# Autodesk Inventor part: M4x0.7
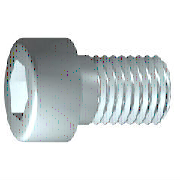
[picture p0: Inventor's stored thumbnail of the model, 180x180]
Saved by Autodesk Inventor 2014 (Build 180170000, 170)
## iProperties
Created: 2009-02
Part Number: M4x0.7
Material: Steel, Mild
Description: 6각머리 태핑 나사
Document SubType Name: Modeling
Standard: KS B 1003
Standards Organization: KS
Language: ko-KR
Size Designation: M 4 x 12
Categories: <MemberInstance><Categories><Category DisplayName="조임쇠" InternalName="e4da775c-781d-43d5-af7c-5136215cf5a6" Mnemonic="FSTN"><Category DisplayName="볼트" InternalN
Density: 1 g/cm^3
Checked By: KYOUNG IL JANG
Vendor: CBT Solutions
Designer: KYOUNG IL JANG
Appearance: _시험-금속-강(연마)
Manager: KYOUNG IL JANG
Company: 한국ATC센터
IsCustomPart: 0
Author: KYOUNG IL JANG
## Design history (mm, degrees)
revolve "본체" stored, may be unused: angle "d10" = 90 deg
sketch "스케치2"
  geometry: L1 (0, -4.9)-(0, 4.9) reference; L2 (-4.9, 0)-(4.9, 0) reference; L3 (1.732, 0)-(0.866, -1.5); L4 (0.866, -1.5)-(-0.866, -1.5); L5 (-0.866, -1.5)-(-1.732, 0); L6 (-1.732, 0)-(-0.866, 1.5); L7 (-0.866, 1.5)-(0.866, 1.5); L8 (0.866, 1.5)-(1.732, 0); 2 further points
  constraints: 12 end point, 1 coincident, 1 horizontal alignment, 1 point on line, 12 other
extrude "슬롯" join sketch "스케치2" stored distance "d11" = 10; taper "d12" = 0 deg
workplane "Work Plane1"
fillet "Fillet2" dims "d30" = 0.1 (= R)
body "Solid1"
fillet "모깎기1" dims "d17" = 0.4 (= RR)
feature "스레드" dims "d13" = 10.25 (= GEL), "d14" = 0
chamfer "모따기1" distance "d15" = 0.42941 (= -0.5 x SPD + 0.5 x GD); stored, may be unused: second distance "d16" = 0.42941 (= GUL), angle "d27" = 45 deg
sketch "스케치1"
  geometry: L1 (-1, 0)-(12, 0); L2 (12, 0)-(12, 2); L3 (12, 2)-(1.75, 2); L4 (1.75, 2)-(1.32, 2); L5 (1.32, 2)-(0, 2); L6 (0, 2)-(0, 3.5); L7 (0, 3.5)-(-4, 3.5); L8 (-4, 3.5)-(-4, 1.732); L9 (-4, 1.732)-(-2, 1.732); L10 (-2, 1.732)-(-1, 0); L11 (-7.2, 0)-(15.2, 0) reference; L12 (0, -0.7)-(0, 4.2) reference; L13 (1.75, 2)-(0, 2)
  constraints: 22 end point, 6 parallel, 2 collinear, 2 perpendicular, 1 horizontal, 1 point on line
  dimensions: "d1" = 10.25 distance from line of L3.end L2 (= GEL); "d2" = 0.42952 distance of L4.end L3.end (computed from GAL); "d3" = 4 distance between parallel lines of L8 L6 (= KOH); "d4" = 2 distance of L8.end L9.end (= INTI); "d5" = 60 deg angle of L10 L1; "d6" = 4 diameter of L3 L1 (= GD); "d7" = 4 diameter of L5 L1 (= BDM); "d8" = 3.4641 diameter of L9 L1 (= 1.1547 x SW); "d9" = 7 diameter of L7 L1 (= KOD); "d26" = 12 distance between parallel lines of L12 L2 (= NLG)
other parameters: "GD" = 4 (= NND) [user parameter; used in 2 equation terms], "NLG" = 12 [user parameter; used in 1 equation term], "GEL" = 10.25 [user parameter; used in 2 equation terms], "KOD" = 7 [user parameter; used in 1 equation term], "KOH" = 4 [user parameter; used in 1 equation term], "INTI" = 2 [user parameter; used in 1 equation term], "GAL" = 0.42941 (= 0.61345 x PTC) [user parameter; used in 1 equation term], "GUL" = 0.42941 (= 0.61345 x PTC) [user parameter; used in 1 equation term], "BDM" = 4 (= NND) [user parameter; used in 1 equation term], "SW" = 3 [user parameter; used in 2 equation terms], "RR" = 0.4 [user parameter; used in 1 equation term], "SPD" = 3.14117 (= NND - 1.2269 x PTC) [user parameter; used in 1 equation term], "d19" = 0, "d28" = 0, "d29" = 0, "R" = 0.1 [user parameter; used in 1 equation term], "PHH" = 0.2 [user parameter], "GD1" = 3.14117 (= THREADDIA - 1.2269 x PTC) [user parameter], "THREADDIA" = 4 [user parameter; used in 1 equation term], "FAWI" = 45 deg [user parameter], "TPU" = 14.28571 (computed from PTC) [user parameter], "PTC" = 0.7 [user parameter; used in 5 equation terms], "NND" = 4 [user parameter; used in 3 equation terms], "TOA" = 30 deg [user parameter], "E0" = 3.465 (= 1.155 x SW) [user parameter]
